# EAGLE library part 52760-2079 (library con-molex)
MOLEX Connector SD-52760-**79 Source: 52760-1079_sd molex.pdf
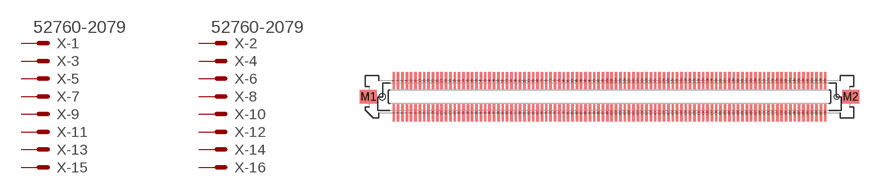
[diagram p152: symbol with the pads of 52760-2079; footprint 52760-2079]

Designator prefix X; gates -1=MV -2=MV -3=M -4=M -5=M -6=M -7=M -8=M -9=M -10=M -11=M -12=M -13=M -14=M -15=M -16=M -17=M -18=M -19=M -20=M -21=M -22=M -23=M -24=M -25=M -26=M -27=M -28=M -29=M -30=M -31=M -32=M -33=M -34=M -35=M -36=M -37=M -38=M -39=M -40=M -41=M -42=M -43=M -44=M -45=M -46=M -47=M -48=M -49=M -50=M -51=M -52=M -53=M -54=M -55=M -56=M -57=M -58=M -59=M -60=M -61=M -62=M -63=M -64=M -65=M -66=M -67=M -68=M -69=M -70=M -71=M -72=M -73=M -74=M -75=M -76=M -77=M -78=M -79=M -80=M -81=M -82=M -83=M -84=M -85=M -86=M -87=M -88=M -89=M -90=M -91=M -92=M -93=M -94=M -95=M -96=M -97=M -98=M -99=M -100=M -101=M -102=M -103=M -104=M -105=M -106=M -107=M -108=M -109=M -110=M -111=M -112=M -113=M -114=M -115=M -116=M -117=M -118=M -119=M -120=M -121=M -122=M -123=M -124=M -125=M -126=M -127=M -128=M -129=M -130=M -131=M -132=M -133=M -134=M -135=M -136=M -137=M -138=M -139=M -140=M -141=M -142=M -143=M -144=M -145=M -146=M -147=M -148=M -149=M -150=M -151=M -152=M -153=M -154=M -155=M -156=M -157=M -158=M -159=M -160=M -161=M -162=M -163=M -164=M -165=M -166=M -167=M -168=M -169=M -170=M -171=M -172=M -173=M -174=M -175=M -176=M -177=M -178=M -179=M -180=M -181=M -182=M -183=M -184=M -185=M -186=M -187=M -188=M -189=M -190=M -191=M -192=M -193=M -194=M -195=M -196=M -197=M -198=M -199=M -200=M

## 52760-2079 (MPN: 52760-2079; OC_FARNELL: unknown; OC_NEWARK: 92M6436)  [52760-2079]
1  -1:S  pas
2  -2:S  pas
3  -3:S  pas
4  -4:S  pas
5  -5:S  pas
6  -6:S  pas
7  -7:S  pas
8  -8:S  pas
9  -9:S  pas
10  -10:S  pas
11  -11:S  pas
12  -12:S  pas
13  -13:S  pas
14  -14:S  pas
15  -15:S  pas
16  -16:S  pas
17  -17:S  pas
18  -18:S  pas
19  -19:S  pas
20  -20:S  pas
21  -21:S  pas
22  -22:S  pas
23  -23:S  pas
24  -24:S  pas
25  -25:S  pas
26  -26:S  pas
27  -27:S  pas
28  -28:S  pas
29  -29:S  pas
30  -30:S  pas
31  -31:S  pas
32  -32:S  pas
33  -33:S  pas
34  -34:S  pas
35  -35:S  pas
36  -36:S  pas
37  -37:S  pas
38  -38:S  pas
39  -39:S  pas
40  -40:S  pas
41  -41:S  pas
42  -42:S  pas
43  -43:S  pas
44  -44:S  pas
45  -45:S  pas
46  -46:S  pas
47  -47:S  pas
48  -48:S  pas
49  -49:S  pas
50  -50:S  pas
51  -51:S  pas
52  -52:S  pas
53  -53:S  pas
54  -54:S  pas
55  -55:S  pas
56  -56:S  pas
57  -57:S  pas
58  -58:S  pas
59  -59:S  pas
60  -60:S  pas
61  -61:S  pas
62  -62:S  pas
63  -63:S  pas
64  -64:S  pas
65  -65:S  pas
66  -66:S  pas
67  -67:S  pas
68  -68:S  pas
69  -69:S  pas
70  -70:S  pas
71  -71:S  pas
72  -72:S  pas
73  -73:S  pas
74  -74:S  pas
75  -75:S  pas
76  -76:S  pas
77  -77:S  pas
78  -78:S  pas
79  -79:S  pas
80  -80:S  pas
81  -81:S  pas
82  -82:S  pas
83  -83:S  pas
84  -84:S  pas
85  -85:S  pas
86  -86:S  pas
87  -87:S  pas
88  -88:S  pas
89  -89:S  pas
90  -90:S  pas
91  -91:S  pas
92  -92:S  pas
93  -93:S  pas
94  -94:S  pas
95  -95:S  pas
96  -96:S  pas
97  -97:S  pas
98  -98:S  pas
99  -99:S  pas
100  -100:S  pas
101  -101:S  pas
102  -102:S  pas
103  -103:S  pas
104  -104:S  pas
105  -105:S  pas
106  -106:S  pas
107  -107:S  pas
108  -108:S  pas
109  -109:S  pas
110  -110:S  pas
111  -111:S  pas
112  -112:S  pas
113  -113:S  pas
114  -114:S  pas
115  -115:S  pas
116  -116:S  pas
117  -117:S  pas
118  -118:S  pas
119  -119:S  pas
120  -120:S  pas
121  -121:S  pas
122  -122:S  pas
123  -123:S  pas
124  -124:S  pas
125  -125:S  pas
126  -126:S  pas
127  -127:S  pas
128  -128:S  pas
129  -129:S  pas
130  -130:S  pas
131  -131:S  pas
132  -132:S  pas
133  -133:S  pas
134  -134:S  pas
135  -135:S  pas
136  -136:S  pas
137  -137:S  pas
138  -138:S  pas
139  -139:S  pas
140  -140:S  pas
141  -141:S  pas
142  -142:S  pas
143  -143:S  pas
144  -144:S  pas
145  -145:S  pas
146  -146:S  pas
147  -147:S  pas
148  -148:S  pas
149  -149:S  pas
150  -150:S  pas
151  -151:S  pas
152  -152:S  pas
153  -153:S  pas
154  -154:S  pas
155  -155:S  pas
156  -156:S  pas
157  -157:S  pas
158  -158:S  pas
159  -159:S  pas
160  -160:S  pas
161  -161:S  pas
162  -162:S  pas
163  -163:S  pas
164  -164:S  pas
165  -165:S  pas
166  -166:S  pas
167  -167:S  pas
168  -168:S  pas
169  -169:S  pas
170  -170:S  pas
171  -171:S  pas
172  -172:S  pas
173  -173:S  pas
174  -174:S  pas
175  -175:S  pas
176  -176:S  pas
177  -177:S  pas
178  -178:S  pas
179  -179:S  pas
180  -180:S  pas
181  -181:S  pas
182  -182:S  pas
183  -183:S  pas
184  -184:S  pas
185  -185:S  pas
186  -186:S  pas
187  -187:S  pas
188  -188:S  pas
189  -189:S  pas
190  -190:S  pas
191  -191:S  pas
192  -192:S  pas
193  -193:S  pas
194  -194:S  pas
195  -195:S  pas
196  -196:S  pas
197  -197:S  pas
198  -198:S  pas
199  -199:S  pas
200  -200:S  pas

## Footprint 52760-2079 (pad centres in mm)
MOLEX Connector SD-52760-**79 Source: 52760-1079_sd molex.pdf
smd 0.35 x 2.5: 1 -31.433,-2.35; 2 -31.433,2.35; 3 -30.797,-2.35; 4 -30.797,2.35; 5 -30.163,-2.35; 6 -30.163,2.35; 7 -29.527,-2.35; 8 -29.527,2.35; 9 -28.892,-2.35; 10 -28.892,2.35; 11 -28.258,-2.35; 12 -28.258,2.35; 13 -27.622,-2.35; 14 -27.622,2.35; 15 -26.988,-2.35; 16 -26.988,2.35; 17 -26.352,-2.35; 18 -26.352,2.35; 19 -25.718,-2.35; 20 -25.718,2.35; 21 -25.082,-2.35; 22 -25.082,2.35; 23 -24.448,-2.35; 24 -24.448,2.35; 25 -23.812,-2.35; 26 -23.812,2.35; 27 -23.177,-2.35; 28 -23.177,2.35; 29 -22.543,-2.35; 30 -22.543,2.35; 31 -21.907,-2.35; 32 -21.907,2.35; 33 -21.273,-2.35; 34 -21.273,2.35; 35 -20.637,-2.35; 36 -20.637,2.35; 37 -20.003,-2.35; 38 -20.003,2.35; 39 -19.367,-2.35; 40 -19.367,2.35; 41 -18.733,-2.35; 42 -18.733,2.35; 43 -18.098,-2.35; 44 -18.098,2.35; 45 -17.462,-2.35; 46 -17.462,2.35; 47 -16.828,-2.35; 48 -16.828,2.35; 49 -16.192,-2.35; 50 -16.192,2.35; 51 -15.557,-2.35; 52 -15.557,2.35; 53 -14.922,-2.35; 54 -14.922,2.35; 55 -14.287,-2.35; 56 -14.287,2.35; 57 -13.652,-2.35; 58 -13.652,2.35; 59 -13.018,-2.35; 60 -13.018,2.35; 61 -12.383,-2.35; 62 -12.383,2.35; 63 -11.748,-2.35; 64 -11.748,2.35; 65 -11.113,-2.35; 66 -11.113,2.35; 67 -10.477,-2.35; 68 -10.477,2.35; 69 -9.842,-2.35; 70 -9.842,2.35; 71 -9.207,-2.35; 72 -9.207,2.35; 73 -8.572,-2.35; 74 -8.572,2.35; 75 -7.938,-2.35; 76 -7.938,2.35; 77 -7.303,-2.35; 78 -7.303,2.35; 79 -6.668,-2.35; 80 -6.668,2.35; 81 -6.032,-2.35; 82 -6.032,2.35; 83 -5.397,-2.35; 84 -5.397,2.35; 85 -4.763,-2.35; 86 -4.763,2.35; 87 -4.128,-2.35; 88 -4.128,2.35; 89 -3.493,-2.35; 90 -3.493,2.35; 91 -2.857,-2.35; 92 -2.857,2.35; 93 -2.223,-2.35; 94 -2.223,2.35; 95 -1.587,-2.35; 96 -1.587,2.35; 97 -0.953,-2.35; 98 -0.953,2.35; 99 -0.318,-2.35; 100 -0.318,2.35; 101 0.318,-2.35; 102 0.318,2.35; 103 0.953,-2.35; 104 0.953,2.35; 105 1.587,-2.35; 106 1.587,2.35; 107 2.223,-2.35; 108 2.223,2.35; 109 2.857,-2.35; 110 2.857,2.35; 111 3.493,-2.35; 112 3.493,2.35; 113 4.128,-2.35; 114 4.128,2.35; 115 4.763,-2.35; 116 4.763,2.35; 117 5.397,-2.35; 118 5.397,2.35; 119 6.032,-2.35; 120 6.032,2.35; 121 6.668,-2.35; 122 6.668,2.35; 123 7.303,-2.35; 124 7.303,2.35; 125 7.938,-2.35; 126 7.938,2.35; 127 8.572,-2.35; 128 8.572,2.35; 129 9.207,-2.35; 130 9.207,2.35; 131 9.842,-2.35; 132 9.842,2.35; 133 10.477,-2.35; 134 10.477,2.35; 135 11.113,-2.35; 136 11.113,2.35; 137 11.748,-2.35; 138 11.748,2.35; 139 12.383,-2.35; 140 12.383,2.35; 141 13.018,-2.35; 142 13.018,2.35; 143 13.652,-2.35; 144 13.652,2.35; 145 14.287,-2.35; 146 14.287,2.35; 147 14.922,-2.35; 148 14.922,2.35; 149 15.557,-2.35; 150 15.557,2.35; 151 16.192,-2.35; 152 16.192,2.35; 153 16.828,-2.35; 154 16.828,2.35; 155 17.462,-2.35; 156 17.462,2.35; 157 18.098,-2.35; 158 18.098,2.35; 159 18.733,-2.35; 160 18.733,2.35; 161 19.367,-2.35; 162 19.367,2.35; 163 20.003,-2.35; 164 20.003,2.35; 165 20.637,-2.35; 166 20.637,2.35; 167 21.273,-2.35; 168 21.273,2.35; 169 21.907,-2.35; 170 21.907,2.35; 171 22.543,-2.35; 172 22.543,2.35; 173 23.177,-2.35; 174 23.177,2.35; 175 23.812,-2.35; 176 23.812,2.35; 177 24.448,-2.35; 178 24.448,2.35; 179 25.082,-2.35; 180 25.082,2.35; 181 25.718,-2.35; 182 25.718,2.35; 183 26.352,-2.35; 184 26.352,2.35; 185 26.988,-2.35; 186 26.988,2.35; 187 27.622,-2.35; 188 27.622,2.35; 189 28.258,-2.35; 190 28.258,2.35; 191 28.892,-2.35; 192 28.892,2.35; 193 29.527,-2.35; 194 29.527,2.35; 195 30.163,-2.35; 196 30.163,2.35; 197 30.797,-2.35; 198 30.797,2.35; 199 31.433,-2.35; 200 31.433,2.35
smd 2.5 x 2: M1 -35.125,0; M2 35.125,0
hole 0.9 at -33.085,0
hole 0.7 at 33.085,0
